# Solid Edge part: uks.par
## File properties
Author: Mac
Template: Normal.par
Last saved by: Mac
Revision: 2
Application: Solid Edge
Material: Aluminum, 1060
Face Style: Aluminum
Fill Style: ANSI38(Aluminum)
Virtual Style: Polished aluminum
Coef. of Thermal Exp: 2.3e-05
Thermal Conductivity: 221.0
Specific Heat: 920.0
Modulus of Elasticity: 68947570000.0
Poission's Ratio: 0.33
Yield Stress: 27579028.0
Ultimate Stress: 68947570.0
Elongation: 0.0
Density: 2712,000 kg/m^3
Accuracy: 0,990
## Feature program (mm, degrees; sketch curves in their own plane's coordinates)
sketch for "unnamed Protrusion 1" #1 plane through (0, 0, 0) normal (0, 0, 1) x-axis (1, 0, 0)
  line (0, -19.11) -> (23.3, -19.11)
  line (23.3, -19.11) -> (23.3, 19.31)
  line (23.3, 19.31) -> (0, 19.31)
  line (0, 19.31) -> (0, -19.11)
sketch for "unnamed Protrusion 1" #2 plane through (0, 0, 0) normal (0, 0, 1) x-axis (1, 0, 0)
  line (0.8, -18.31) -> (0.8, 18.51)
  line (0.8, 18.51) -> (22.5, 18.51)
  line (22.5, 18.51) -> (22.5, -18.31)
  line (22.5, -18.31) -> (0.8, -18.31)
  dimension (linear) = 22.5
  dimension (linear) = 22.5
extrude "unnamed Protrusion 1" add finite 0.55 along +normal
thinwall "Thinwall_1"  Thickness = 0.04 mm
sketch for "unnamed Protrusion 2" #1 plane through (11.65, 0.1, 0.51) normal (0, 0, -1) x-axis (1, 0, 0)
  circle centre (11.15, 19.01) radius 0.08
sketch for "unnamed Protrusion 2" #2 plane through (11.65, 0.1, 0.51) normal (0, 0, -1) x-axis (1, 0, 0)
  circle centre (-11.15, -19.01) radius 0.08
sketch for "unnamed Protrusion 2" #3 plane through (11.65, 0.1, 0.51) normal (0, 0, -1) x-axis (1, 0, 0)
  circle centre (11.15, -19.01) radius 0.08
sketch for "unnamed Protrusion 2" #4 plane through (11.65, 0.1, 0.51) normal (0, 0, -1) x-axis (1, 0, 0)
  circle centre (-11.15, 19.01) radius 0.08
  dimension (linear) = 11.15
  dimension (linear) = 11.15
  dimension (linear) = 11.15
  dimension (linear) = 11.15
extrude "unnamed Protrusion 2" add through along +normal
fillet "Round_1" radius 0.01
sketch for "ExtrudedProtrusion_3" plane through (0, 0, 0.23) normal (0, 0, 1) x-axis (1, 0, 0)
  line (0.8, 18.51) -> (0.8, -18.31)
  line (0.8, -18.31) -> (22.5, -18.31)
  line (22.5, -18.31) -> (22.5, 18.51)
  line (22.5, 18.51) -> (0.8, 18.51)
extrude "ExtrudedProtrusion_3" add finite 0.2 symmetric  Profile_Plane1_Distance = 0.23 mm
sketch for "ExtrudedProtrusion_4" plane through (11.65, 0.1, 0.55) normal (0, 0, 1) x-axis (-1, 0, 0)
  line (-10.86, 1) -> (-11.64, 1)
  line (-11.64, -1) -> (-11.64, 1)
  line (-10.86, -1) -> (-11.64, -1)
  line (-10.86, 1) -> (-10.86, -1)
extrude "ExtrudedProtrusion_4" add finite 0.06 along +normal
sketch for "ExtrudedProtrusion_5" plane through (22.9, 0.1, 0.61) normal (0, 0, 1) x-axis (1, 0, 0)
  circle centre (0, 0.4552) radius 0.15
extrude "ExtrudedProtrusion_5" add finite 0.6 along +normal
sketch for "ExtrudedProtrusion_6" plane through (22.9, 0.5552, 1.21) normal (0, 0, 1) x-axis (1, 0, 0)
  line (-1.85, 0.0815) -> (-1.85, -0.0792)
  arc centre (-1.8108, -0.0792) radius 0.0392 from (-1.85, -0.0792) to (-1.8115, -0.1184) ccw
  line (0, -0.15) -> (-1.8115, -0.1184)
  line (-0.0052, 0.1499) -> (-1.8138, 0.1183)
  arc centre (-1.8131, 0.0815) radius 0.0369 from (-1.85, 0.0815) to (-1.8138, 0.1183) cw
  dimension (linear) = 0.15
extrude "ExtrudedProtrusion_6" add finite 0.06 along +normal
sketch for "ExtrudedProtrusion_7" #1 plane through (22.9, 0.1, 0.61) normal (0, 0, 1) x-axis (1, 0, 0)
  line (-0.0065, -0.2147) -> (-0.0065, -0.3144)
  arc centre (-0.0165, -0.3144) radius 0.01 from (-0.0265, -0.3144) to (-0.0065, -0.3144) ccw
  line (-0.0265, -0.3144) -> (-0.0265, -0.2147)
  arc centre (-0.0165, -0.2147) radius 0.01 from (-0.0265, -0.2147) to (-0.0065, -0.2147) cw
sketch for "ExtrudedProtrusion_7" #2 plane through (22.9, 0.1, 0.61) normal (0, 0, 1) x-axis (1, 0, 0)
  line (-0.0765, -0.3848) -> (-0.0765, -0.5375)
  arc centre (-0.0165, -0.5375) radius 0.06 from (0.0435, -0.5375) to (-0.0765, -0.5375) cw
  line (0.0435, -0.3823) -> (0.0435, -0.5375)
  arc centre (0.1239, -0.3823) radius 0.0804 from (0.0435, -0.3823) to (0.0636, -0.3291) cw
  arc centre (-0.1638, -0.3848) radius 0.0873 from (-0.0765, -0.3848) to (-0.0976, -0.328) ccw
  dimension (linear) = 0.0165
extrude "ExtrudedProtrusion_7" add finite 0.06 along +normal
sketch for "unnamed Cutout 1" plane through (22.8835, -0.2746, 0.67) normal (0, 0, 1) x-axis (0, -1, 0)
  line (-0.1599, 0.01) -> (-0.0602, 0.01)
  arc centre (-0.0602, 0) radius 0.01 from (-0.0602, 0.01) to (-0.0602, -0.01) cw
  line (-0.0602, -0.01) -> (-0.1599, -0.01)
  arc centre (-0.1599, 0) radius 0.01 from (-0.1599, -0.01) to (-0.1599, 0.01) cw
extrude "unnamed Cutout 1" cut through along -normal
fillet "Round_9" radius 0.02
fillet "Round_12" radius 0.06
Other named dimensions: "Round_8": Radii1 = 0.02 mm | "Round_13": Radii1 = 0.06 mm
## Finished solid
Body 1: sheet body, 50 faces, 115 edges, 68 vertices.
  Faces by surface: cylinder 23, plane 15, torus 10, blend 2
  Edges by curve: line 57, circle 49, ellipse 4, intersection 4, curve on surface 1
Body 2: sheet body, 1 face, 4 edges, 4 vertices.
  Faces by surface: plane 1
  Edges by curve: line 4
Body 3: solid body, 106 faces, 253 edges, 148 vertices.
  Faces by surface: cylinder 53, plane 41, torus 10, blend 2
  Edges by curve: line 151, circle 77, ellipse 20, intersection 4, curve on surface 1
Bounding box of the edges (mm; curved faces can reach further): 24.400 x 38.420 x 1.990, from (0, -19.11, -0.72) to (24.4, 19.31, 1.27).
Cylindrical faces by radius (mm): R0.01 x30, R0.02 x26, R0.0369 x2, R0.0392 x2, R0.06 x4, R0.08 x4, R0.0804 x2, R0.0873 x2, R0.1068 x2, R0.15 x2
Toroidal faces (ring radius, tube radius in mm): R0.0169 r0.02 x4, R0.0192 r0.02 x4, R0.04 r0.02 x2, R0.0868 r0.02 x2, R0.1004 r0.02 x2, R0.1073 r0.02 x2, R0.13 r0.02 x2, R0.21 r0.06 x2
Planar faces by outward normal: +x 9, +y 5, +z 6, -x 10, -y 5, -z 4, oblique 2
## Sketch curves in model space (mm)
line (23.3, 2.1062, 0.275) -> (23.3, -0.196, 0.275)
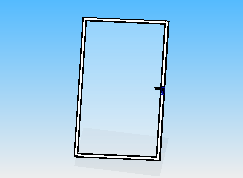
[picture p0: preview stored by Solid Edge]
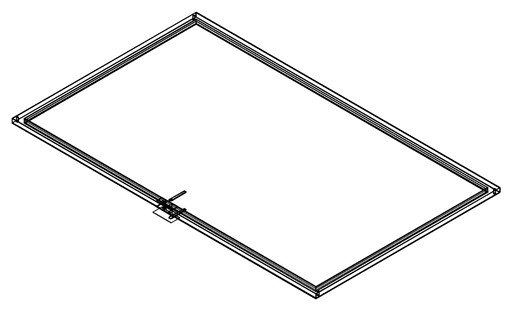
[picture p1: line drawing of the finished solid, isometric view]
